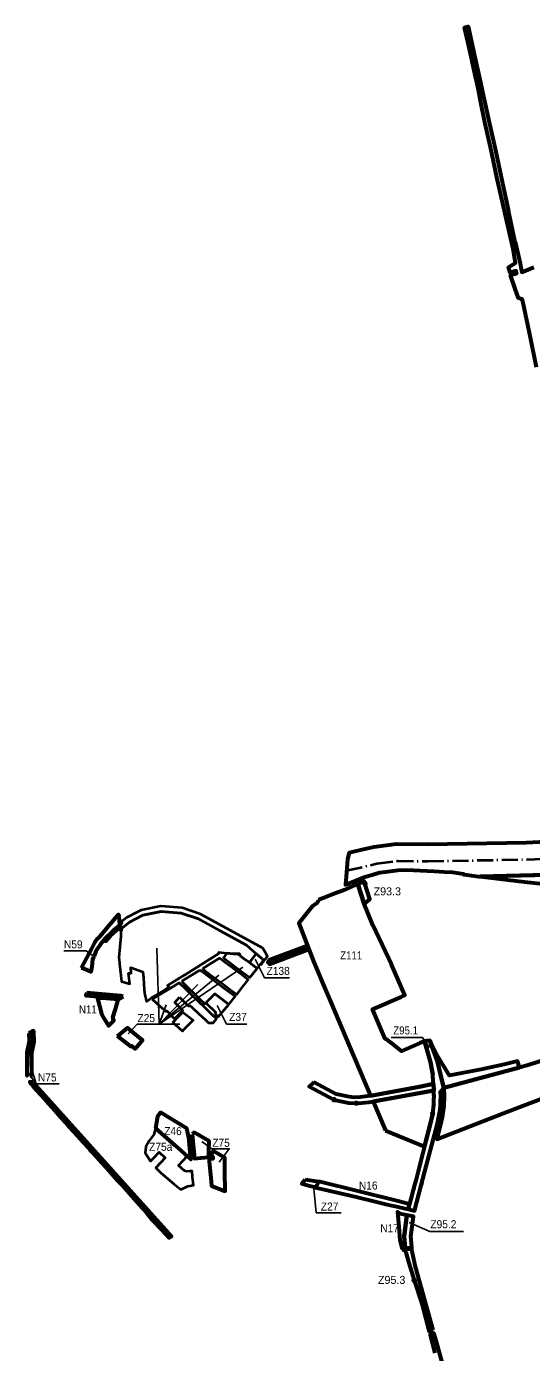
# Model space of a CAD drawing. Extents: x -650277 to -643422, y -1073980 to -1066720.
# Drawn here: x -650277 to -648765, y -1070696 to -1066720 of the extents above; entities that cross this region are included whole.
import ezdxf

# ---------------------------------------------------------------- set-up
doc = ezdxf.new("R2010")
doc.units = 0
doc.header["$LTSCALE"] = 9.6
doc.header["$PDMODE"] = 32
doc.header["$PDSIZE"] = 4.8
doc.linetypes.add('DOT_DASHED', pattern=[7.7, 5, -1.2, 0.3, -1.2])
for name, color, linetype, lineweight in [('1', 7, 'Continuous', 60), ('12', 7, 'Continuous', 60), ('13', 7, 'Continuous', 60), ('15', 7, 'Continuous', 60), ('18', 7, 'Continuous', 60), ('2', 7, 'Continuous', 40), ('24', 7, 'Continuous', 60), ('3', 7, 'Continuous', 60), ('40', 7, 'Continuous', 60), ('42', 7, 'Continuous', 60), ('48', 7, 'Continuous', 60), ('59', 7, 'Continuous', 25), ('60', 7, 'Continuous', 60), ('62', 7, 'DOT_DASHED', 40), ('63', 7, 'Continuous', 25), ('7', 7, 'Continuous', 60), ('9', 7, 'Continuous', 60)]:
    doc.layers.add(name, color=color, linetype=linetype, lineweight=lineweight)

msp = doc.modelspace()

# ---------------------------------------------------------------- linework, layer by layer
at = {"layer": '1'}
for points in [[(-650004.59, -1069747.27), (-649974.86, -1069721.96), (-649966.52, -1069728.87), (-649929.38, -1069759.65), (-649951.56, -1069785.42), (-649963, -1069776.7), (-649965, -1069778.7)], [(-649442.63, -1070176.69), (-649402.29, -1070182.92), (-649404.2, -1070187.43), (-649412.2, -1070200.71), (-649433.3, -1070195.89), (-649453.27, -1070190.02), (-649446.19, -1070180.76)]]:
    msp.add_lwpolyline(points, close=True, dxfattribs=at)
at = {"layer": '12'}
msp.add_lwpolyline([(-649891.21, -1070022.68), (-649832.007, -1070074.751), (-649784.87, -1070116.76), (-649791.31, -1070051.51), (-649797.45, -1070023.77), (-649876.31, -1069975.93), (-649884.59, -1069988.57)], close=True, dxfattribs=at)
at = {"layer": '13'}
msp.add_line((-649202.375, -1070030.469), (-649085.737, -1070078.201), dxfattribs=at)
for points in [[(-649057.868, -1069910.51), (-649239.635, -1069943.094), (-649202.375, -1070030.469)], [(-649085.737, -1070078.201), (-649066.487, -1070004.267), (-649061.139, -1069979.254), (-649061.138, -1069979.243)]]:
    msp.add_lwpolyline(points, dxfattribs=at)
msp.add_arc((-649347.129, -1069931.193), 290, 350.46253, 4.08974, dxfattribs=at)
msp.add_point((-649061.138, -1069979.243), dxfattribs=at)
at = {"layer": '15'}
msp.add_line((-649057.868, -1069910.51), (-649058.82, -1069890.548), dxfattribs=at)
for points in [[(-648749.97, -1067741.49), (-648767.84, -1067652.98), (-648791.68, -1067543.78), (-648792.97, -1067537.86), (-648804.08, -1067534.88), (-648813.94, -1067506.27), (-648827.86, -1067465.86), (-648809.65, -1067459.77), (-648809.97, -1067458.52), (-648811.21, -1067453.52), (-648811.4, -1067452.79), (-648829.54, -1067458.42), (-648834.01, -1067441.81), (-648812.91, -1067429.16), (-648820.39, -1067386.83), (-648844.16, -1067281.37), (-648845.94, -1067272.85), (-648867.82, -1067176.66), (-648884.26, -1067099.63), (-648899.1, -1067033.34), (-648905.06, -1067006.7), (-648917.76, -1066942.65), (-648924.32, -1066909.55), (-648936.7, -1066852.52), (-648944.75, -1066815.41), (-648955.15, -1066770.11), (-648965.39, -1066723.15), (-648959.88, -1066721.59), (-648954.86, -1066720.16), (-648935.19, -1066812.53), (-648918.27, -1066888.41), (-648914.11, -1066907.05), (-648893.02, -1067002.5), (-648872.31, -1067095.5), (-648851.87, -1067191.04), (-648835.29, -1067268.93), (-648833.66, -1067276.77), (-648816.06, -1067361.71), (-648813.81, -1067365.91), (-648799.58, -1067430.4), (-648796.8, -1067443.1), (-648795.88, -1067447.21), (-648794.7, -1067452.46), (-648793.71, -1067456.88), (-648757.97, -1067441.51)], [(-650096.627, -1069617.746), (-650099.55, -1069625.53), (-650002.39, -1069633.65)], [(-649987.49, -1069628.6), (-649994.913, -1069626.246), (-650096.627, -1069617.746)], [(-650002.39, -1069633.65), (-650002.65, -1069637.14), (-649987.49, -1069628.6)], [(-649417.234, -1069885.193), (-649418.94, -1069887.36), (-649430.515, -1069898.514), (-649356.458, -1069937.945)], [(-649246.81, -1069926.27), (-649278.492, -1069930.573), (-649296.851, -1069931.092), (-649310.738, -1069929.342), (-649350.222, -1069920.873), (-649417.234, -1069885.193)], [(-649058.82, -1069890.548), (-649101.89, -1069898.73), (-649246.81, -1069926.27)], [(-649356.458, -1069937.945), (-649312.646, -1069947.342), (-649289.95, -1069948.146)], [(-649289.95, -1069948.146), (-649282.437, -1069948.342), (-649251.805, -1069945.276), (-649239.635, -1069943.094), (-649057.868, -1069910.51)]]:
    msp.add_lwpolyline(points, dxfattribs=at)
for points in [[(-650025.31, -1069446.49), (-649998.512, -1069422.926), (-649999.01, -1069415.628), (-650018.873, -1069431.749), (-650043.521, -1069455.69), (-650045.72, -1069459.1), (-650040.012, -1069461.999)], [(-649547.733, -1069530.185), (-649431.761, -1069486.57), (-649435.578, -1069476.772), (-649550.53, -1069519.68), (-649554.83, -1069525), (-649551.32, -1069528.49), (-649549.69, -1069530.14), (-649548.881, -1069530.963)], [(-648800.85, -1069841.52), (-648806.946, -1069821.79), (-648846.924, -1069832.58), (-648916.03, -1069847.12), (-649010.55, -1069865.09), (-649049.22, -1069801.23), (-649069.4, -1069760.67), (-649048, -1069820), (-649032.928, -1069882.782), (-649028.017, -1069902.109)]]:
    msp.add_lwpolyline(points, close=True, dxfattribs=at)
for p in [(-649356.458, -1069937.945), (-649289.95, -1069948.146)]:
    msp.add_point(p, dxfattribs=at)
at = {"layer": '18'}
for points in [[(-649781.53, -1070041.2), (-649774.45, -1070113.92), (-649754.82, -1070111.89), (-649731.12, -1070109.96), (-649730.96, -1070094.91), (-649730.89, -1070088.96), (-649730.6, -1070061.98), (-649774.73, -1070035.58)], [(-649730.57, -1070115.76), (-649730, -1070122.01), (-649726.22, -1070162.75), (-649725.49, -1070170.64), (-649723.17, -1070195.81), (-649682.04, -1070211.58), (-649683.12, -1070154.14), (-649682.98, -1070132.1), (-649683.57, -1070112.05), (-649717.72, -1070091.61), (-649718.71, -1070093.35), (-649724.36, -1070099.03), (-649719.69, -1070108.94), (-649719.24, -1070114.87)]]:
    msp.add_lwpolyline(points, close=True, dxfattribs=at)
at = {"layer": '2'}
for points in [[(-649639.18, -1069505.96), (-649637.69, -1069506.15), (-649628.36, -1069513.11), (-649609.93, -1069526.87), (-649598.004, -1069510.814), (-649589.257, -1069499.905), (-649619, -1069474), (-649697.525, -1069431.522), (-649762.488, -1069395.854), (-649814.067, -1069377.972), (-649874.391, -1069373.859), (-649929.015, -1069384.784), (-649968.465, -1069405.189), (-649994.293, -1069425.949), (-649994.53, -1069447.61), (-650000.59, -1069511.15), (-649998.81, -1069527.07), (-649998.5, -1069529.88), (-649992.59, -1069582.88), (-649967.81, -1069590.74), (-649971.38, -1069558.79), (-649963.43, -1069557.91), (-649965.26, -1069541.51), (-649928.48, -1069554.57), (-649927.3, -1069572.44)], [(-649927.3, -1069572.44), (-649924.62, -1069608.53), (-649923.17, -1069623.14), (-649918.35, -1069643.45), (-649918.35, -1069643.45), (-649903.292, -1069632.541), (-649877.129, -1069617.006), (-649850.24, -1069600.295), (-649855.34, -1069595.8), (-649805.22, -1069564.32), (-649801.49, -1069561.98), (-649701.57, -1069499.21), (-649701.7, -1069495.89), (-649677.02, -1069498.32), (-649658.01, -1069500.19), (-649647.45, -1069500.23), (-649638.81, -1069500.26), (-649639.18, -1069505.96)], [(-649677.02, -1069498.32), (-649687.77, -1069512.44), (-649667.74, -1069527.4), (-649649.31, -1069541.16)], [(-649639.18, -1069505.96), (-649638.81, -1069500.26), (-649647.45, -1069500.23), (-649658.01, -1069500.19), (-649677.02, -1069498.32)], [(-649609.93, -1069526.87), (-649628.36, -1069513.11), (-649637.69, -1069506.15), (-649639.18, -1069505.96)], [(-649597.997, -1069510.805), (-649598.004, -1069510.814), (-649609.93, -1069526.87), (-649586.82, -1069544.11)], [(-649597.935, -1069510.728), (-649597.763, -1069510.865), (-649597.997, -1069510.805)], [(-649571.94, -1069529.24), (-649573.922, -1069527.657), (-649567, -1069519), (-649588, -1069501), (-649589.257, -1069499.905), (-649597.935, -1069510.728)], [(-649758.29, -1069549.64), (-649785.72, -1069566.56), (-649812.08, -1069582.83)], [(-649671.39, -1069651.93), (-649652.88, -1069628.36), (-649677.124, -1069610.681), (-649696.91, -1069595.47), (-649718.13, -1069579.63), (-649739.75, -1069563.48), (-649758.29, -1069549.64)], [(-649707.19, -1069577.81), (-649688.76, -1069591.57), (-649670.34, -1069605.34), (-649647.93, -1069622.07), (-649628.8, -1069597.67), (-649613.37, -1069577.98), (-649636.83, -1069560.47), (-649659.26, -1069543.71), (-649681.7, -1069526.96), (-649699.72, -1069513.5), (-649722.6, -1069527.61), (-649749.62, -1069544.29)], [(-649749.62, -1069544.29), (-649748.89, -1069546.2), (-649747.5, -1069547.71), (-649725.62, -1069564.05), (-649707.19, -1069577.81)], [(-649649.31, -1069541.16), (-649630.88, -1069554.92), (-649608.44, -1069571.69), (-649586.82, -1069544.11), (-649609.93, -1069526.87)], [(-649586.82, -1069544.11), (-649576.071, -1069530.398), (-649574.1, -1069531.97), (-649571.94, -1069529.24)], [(-649788.91, -1069654.4), (-649781.09, -1069661.69), (-649761.34, -1069680.08), (-649741.61, -1069698.46), (-649732.52, -1069706.92), (-649717.884, -1069707.295), (-649707.985, -1069695.508), (-649723.97, -1069680.13), (-649743.41, -1069661.43), (-649762.85, -1069642.73), (-649782.03, -1069624.28), (-649801.48, -1069605.57), (-649820.02, -1069587.73), (-649846.38, -1069603.8), (-649900.64, -1069636.78)], [(-649812.08, -1069582.83), (-649811.52, -1069584.44), (-649810.49, -1069585.81), (-649793.12, -1069602.51), (-649776.54, -1069618.46), (-649759.97, -1069634.4)], [(-649833.94, -1069695.239), (-649819.98, -1069680.92), (-649809.47, -1069670.13), (-649833.38, -1069646.08), (-649818.71, -1069630.64)], [(-649818.71, -1069630.64), (-649802.9, -1069645.96), (-649791, -1069657), (-649788.91, -1069654.4)], [(-649740.23, -1069647.14), (-649713.73, -1069620.32), (-649713.73, -1069620.32), (-649693.63, -1069635.33), (-649671.39, -1069651.93)], [(-649900.64, -1069636.78), (-649877.82, -1069656.83), (-649859.96, -1069672.53)], [(-649759.97, -1069634.4), (-649743.39, -1069650.35), (-649740.23, -1069647.14)], [(-649859.96, -1069672.53), (-649859.17, -1069673.22), (-649857.49, -1069671.46), (-649833.94, -1069695.239)]]:
    msp.add_lwpolyline(points, dxfattribs=at)
for points in [[(-649713.73, -1069620.32), (-649713.73, -1069620.32), (-649740.23, -1069647.14), (-649709.94, -1069676.28), (-649712.54, -1069678.98), (-649712.89, -1069679.87), (-649712.51, -1069680.75), (-649703.15, -1069689.75), (-649671.39, -1069651.93), (-649693.63, -1069635.33)], [(-649838.99, -1069706.15), (-649820.64, -1069687.33), (-649808.96, -1069675.34), (-649777.94, -1069699.2), (-649792.13, -1069713.65), (-649807.66, -1069729.46), (-649810.41, -1069732.28), (-649819.9, -1069723.61)], [(-649891.21, -1070022.68), (-649895.45, -1070042.15), (-649910.34, -1070061.29), (-649919.55, -1070079.01), (-649922.3, -1070096.9), (-649905.51, -1070122.35), (-649897.03, -1070113.07), (-649880.42, -1070094.87), (-649862.22, -1070111.54), (-649889.87, -1070141.83), (-649874.94, -1070157.19), (-649835.28, -1070191.27), (-649815.33, -1070206.63), (-649794.37, -1070197.2), (-649777.29, -1070193.57), (-649779.75, -1070168.69), (-649781.436, -1070151.591), (-649787.92, -1070152.23), (-649797.33, -1070153.41), (-649804.29, -1070150.68), (-649821.97, -1070134.58), (-649796.4, -1070106.56)]]:
    msp.add_lwpolyline(points, close=True, dxfattribs=at)
at = {"layer": '24'}
for points in [[(-649321.69, -1069307.61), (-649324.3, -1069308.59), (-649359.48, -1069321.82), (-649389.4, -1069333.35), (-649396.52, -1069336.09), (-649403.92, -1069338.26)], [(-649283.702, -1069294.132), (-649284.695, -1069291.033), (-649300.133, -1069297.95), (-649321.69, -1069307.61)], [(-649060.897, -1069861.994), (-649068, -1069825.147), (-649085.41, -1069762.44), (-649085.41, -1069762.44), (-649099.75, -1069768.575), (-649154.76, -1069792.11), (-649184.05, -1069768.45), (-649200.64, -1069756.53), (-649202.99, -1069754.99), (-649241.11, -1069665.9), (-649155.082, -1069629.097), (-649144.57, -1069624.6), (-649184.1, -1069532.2), (-649240.202, -1069414.528), (-649244.08, -1069404.753), (-649265.774, -1069350.068), (-649283.702, -1069294.132)], [(-649403.92, -1069338.26), (-649403.03, -1069340.66), (-649408.81, -1069349.89), (-649422.19, -1069357.99), (-649462.25, -1069408.32), (-649435.578, -1069476.772), (-649431.761, -1069486.57)], [(-649431.761, -1069486.57), (-649416.52, -1069525.68), (-649409.355, -1069544.517), (-649388.438, -1069594.296), (-649379.32, -1069615.71), (-649364.44, -1069650.55), (-649312.03, -1069773.33)], [(-649312.03, -1069773.33), (-649246.81, -1069926.27), (-649101.89, -1069898.73), (-649058.82, -1069890.548)]]:
    msp.add_lwpolyline(points, dxfattribs=at)
msp.add_arc((-649649.71, -1069919.176), 591.583, 2.77379, 5.54687, dxfattribs=at)
at = {"layer": '3', "lineweight": 40}
for points in [[(-649558.601, -1069502.461), (-649570.03, -1069483.83), (-649688.625, -1069418.156), (-649755.971, -1069381.179), (-649810.846, -1069362.154), (-649875.434, -1069357.751), (-649934.363, -1069369.537), (-649945.397, -1069375.277), (-649977.239, -1069391.714), (-649994.329, -1069405.451)], [(-649994.293, -1069425.949), (-649968.465, -1069405.189), (-649929.015, -1069384.784), (-649874.391, -1069373.859)], [(-649874.391, -1069373.859), (-649814.067, -1069377.972), (-649762.488, -1069395.854), (-649697.525, -1069431.522), (-649619, -1069474), (-649589.257, -1069499.905)], [(-649994.329, -1069405.451), (-649994.329, -1069405.451), (-649994.293, -1069425.949), (-649994.293, -1069425.949)], [(-649589.257, -1069499.905), (-649567, -1069519), (-649573.922, -1069527.657), (-649571.94, -1069529.24), (-649561.17, -1069515.83), (-649555.16, -1069508.07), (-649558.601, -1069502.461)]]:
    msp.add_lwpolyline(points, dxfattribs=at)
at = {"layer": '3'}
msp.add_lwpolyline([(-648722.24, -1069817.54), (-648772.48, -1069832.83), (-648800.85, -1069841.52), (-649028.017, -1069902.109), (-649027.135, -1069928.902), (-649027.953, -1069955.702), (-649032.644, -1069990.371), (-649037.411, -1070011.659), (-649048.918, -1070055.852), (-648931.057, -1070010.171), (-648849.532, -1069978.559), (-648767.83, -1069946.87), (-648562.242, -1069870.301)], dxfattribs=at)
for p in [(-649994.329, -1069405.451), (-649994.293, -1069425.949)]:
    msp.add_point(p, dxfattribs=at)
at = {"layer": '40'}
for points in [[(-650002.65, -1069637.14), (-650050.26, -1069633.65), (-650064.77, -1069633.06), (-650052.88, -1069679.49), (-650047.45, -1069690.69), (-650031.64, -1069715.9), (-650015.53, -1069700.21), (-650018.31, -1069690.89), (-650011.15, -1069665.82)], [(-649160.748, -1070243.413), (-649402.29, -1070182.92), (-649404.2, -1070187.43), (-649412.2, -1070200.71), (-649412.2, -1070200.71), (-649408.24, -1070201.62), (-649372.69, -1070209.74), (-649289.83, -1070229.16), (-649229.8, -1070243.94), (-649197.55, -1070251.65), (-649164.91, -1070258.55), (-649160.54, -1070259.96), (-649134.294, -1070266.095), (-649130.712, -1070250.935)]]:
    msp.add_lwpolyline(points, close=True, dxfattribs=at)
at = {"layer": '42'}
msp.add_lwpolyline([(-650112.18, -1069542.11), (-650081.29, -1069484.35), (-650072.5, -1069466.44), (-650063.12, -1069453.54), (-650062.17, -1069454.05), (-650060.29, -1069451.7), (-650057.49, -1069448.18), (-650026.33, -1069411.47), (-650003.73, -1069384.71), (-650002.11, -1069382.8), (-650001.13, -1069388.13), (-649999.95, -1069397.98), (-649999.01, -1069415.628), (-650018.873, -1069431.749), (-650043.521, -1069455.69), (-650045.72, -1069459.1), (-650055.612, -1069471.639), (-650066.897, -1069487.541), (-650069.369, -1069492.132), (-650074.75, -1069506.133), (-650076.365, -1069510.333), (-650079.264, -1069517.874), (-650080.302, -1069525.418), (-650080.802, -1069530.768), (-650082.963, -1069544.736), (-650084.345, -1069554.773)], close=True, dxfattribs=at)
at = {"layer": '48'}
for points in [[(-650270.059, -1069739.232), (-650269.449, -1069762.714), (-650276.214, -1069796.532), (-650275.76, -1069865.474), (-650274.95, -1069865.62), (-650273.87, -1069809.74), (-650273.78, -1069805.2), (-650273.58, -1069794.48), (-650270.15, -1069778.65), (-650267.22, -1069765.1), (-650265.37, -1069741.61), (-650264.91, -1069735.69)], [(-650260.645, -1069868.536), (-650260.748, -1069867.327), (-650261.204, -1069797.969), (-650254.411, -1069764.006), (-650255.21, -1069733.253), (-650255.716, -1069731.162), (-650259.97, -1069732.29), (-650258.74, -1069750.62), (-650257.77, -1069765.2), (-650262.93, -1069794.84), (-650262.77, -1069805.54), (-650262.7, -1069809.89), (-650261.8, -1069868.33)], [(-650257.713, -1069885.547), (-650266.89, -1069883.7), (-650266.68, -1069886.78), (-650262.64, -1069891.57), (-650257.16, -1069898.07), (-650224.71, -1069934.41), (-650209.51, -1069951.43), (-650192.51, -1069970.47), (-650174.3, -1069990.86), (-650157.87, -1070009.26), (-650151.03, -1070016.84), (-650134.26, -1070035.45), (-650106.76, -1070065.96), (-650091.89, -1070082.46), (-650087.18, -1070087.68), (-650076.72, -1070099.29), (-650051.33, -1070127.45), (-650037.78, -1070142.48), (-650018.41, -1070163.97), (-650005.3, -1070178.51), (-649990.95, -1070194.43), (-649977.05, -1070209.85), (-649946.39, -1070243.87), (-649930.46, -1070261.54), (-649924.15, -1070268.55), (-649913.03, -1070282.44), (-649901.59, -1070296.73), (-649871.28, -1070329.01), (-649850.04, -1070351.64), (-649843.513, -1070347.685)]]:
    msp.add_lwpolyline(points, close=True, dxfattribs=at)
at = {"layer": '59'}
for p, q in [((-649880, -1069711), (-649887, -1069483)), ((-649880, -1069711), (-649629, -1069540)), ((-649880, -1069711), (-649701, -1069564)), ((-649880, -1069711), (-649764, -1069592)), ((-649880, -1069711), (-649818, -1069711)), ((-649410, -1070277), (-649417.769, -1070193.978)), ((-649335, -1070277), (-649410, -1070277))]:
    msp.add_line(p, q, dxfattribs=at)
for points in [[(-649490, -1069572), (-649565, -1069572), (-649593, -1069516)], [(-649946, -1069711), (-649880, -1069711), (-649859, -1069653)], [(-649618, -1069711), (-649678, -1069711), (-649706, -1069655)]]:
    msp.add_lwpolyline(points, dxfattribs=at)
at = {"layer": '60'}
for p, q in [((-649058.858, -1069889.759), (-649057.868, -1069910.51)), ((-649057.134, -1069932.873), (-649057.868, -1069910.51)), ((-649146.163, -1070347.543), (-649145.424, -1070357.637))]:
    msp.add_line(p, q, dxfattribs=at)
for points in [[(-648721.315, -1069164.952), (-648781.015, -1069167.44), (-649076.02, -1069172.683), (-649169.781, -1069171.432), (-649237.512, -1069180.731), (-649277.021, -1069189.913), (-649306.455, -1069196.754), (-649311.633, -1069197.958), (-649316.47, -1069216.91), (-649321.32, -1069281.47), (-649322.09, -1069291.73), (-649322.22, -1069293.54), (-649319.72, -1069292.47), (-649267.5, -1069270.41), (-649242.5, -1069263.3), (-649220.18, -1069257.03), (-649202.63, -1069254.4), (-649165.62, -1069249.43), (-649139.63, -1069248.73), (-649056.95, -1069252.55), (-649026.955, -1069254.366), (-649001.3, -1069255.92), (-648968.49, -1069260.36), (-648968.05, -1069263.06), (-648965.8, -1069262.75), (-648937.91, -1069266.51), (-648924.13, -1069268.21), (-648918.889, -1069268.875), (-648673.267, -1069262.895)], [(-649061.138, -1069979.243), (-649061.138, -1069979.243), (-649061.139, -1069979.254), (-649066.487, -1070004.267), (-649098.65, -1070127.795), (-649110.925, -1070177.113), (-649114.174, -1070189.816), (-649130.712, -1070250.935), (-649134.294, -1070266.095), (-649115.159, -1070270.568), (-649095.152, -1070193.731), (-649093.095, -1070186.132), (-649095.152, -1070193.731), (-649080.924, -1070137.409), (-649080.38, -1070136.996), (-649047.131, -1070009.304), (-649042.468, -1069988.477), (-649042.468, -1069988.477), (-649039.966, -1069973.035), (-649037.98, -1069956.626), (-649037.322, -1069942.129), (-649037.137, -1069928.996), (-649037.665, -1069912.977), (-649028.017, -1069902.109), (-649032.928, -1069882.782), (-649048, -1069820), (-649069.4, -1069760.67), (-649085.41, -1069762.44), (-649068, -1069825.147), (-649060.897, -1069861.994)], [(-649138.43, -1070283.6), (-649146.163, -1070347.543), (-649146.163, -1070347.543)], [(-649125.503, -1070355.837), (-649126.069, -1070348.097), (-649118.257, -1070287.455), (-649138.43, -1070283.6)], [(-649059.951, -1070628.223), (-649112.14, -1070439.152), (-649123.138, -1070388.16), (-649123.385, -1070384.775), (-649145.73, -1070387.91)], [(-649145.424, -1070357.637), (-649143.633, -1070382.123), (-649123.693, -1070380.572), (-649125.503, -1070355.837)], [(-649145.73, -1070387.91), (-649141.48, -1070394.84), (-649132.07, -1070426.81), (-649116.56, -1070479.19)], [(-649116.56, -1070479.19), (-649093.2, -1070549.1), (-649071.33, -1070632.6), (-649059.951, -1070628.223)], [(-649025.129, -1070754.377), (-649047.11, -1070674.743), (-649050.081, -1070663.981), (-649057.338, -1070637.689), (-649068.65, -1070642.23), (-649068.65, -1070642.23), (-649054.31, -1070696.44)]]:
    msp.add_lwpolyline(points, dxfattribs=at)
msp.add_lwpolyline([(-648730.66, -1069290.43), (-648656.242, -1069297.116), (-648673.267, -1069262.895), (-648761.189, -1069265.035), (-648918.889, -1069268.875), (-648909.86, -1069270.02), (-648861.49, -1069275.34), (-648785.92, -1069284.2), (-648730.66, -1069290.43)], close=True, dxfattribs=at)
for centre, radius, start, end in [((-649633.43, -1069918.001), 575.266, 2.81398, 5.58706), ((-649347.129, -1069931.193), 290, 350.46253, 4.08974), ((-649347.129, -1069931.193), 290, 359.66809, 4.08974)]:
    msp.add_arc(centre, radius, start, end, dxfattribs=at)
for p in [(-649145.73, -1070387.91), (-649116.56, -1070479.19)]:
    msp.add_point(p, dxfattribs=at)
at = {"layer": '62'}
msp.add_lwpolyline([(-649319.032, -1069251.01), (-649228.433, -1069229.954), (-649166.697, -1069221.478), (-649075.909, -1069222.689), (-648779.53, -1069217.422), (-648667.088, -1069212.737)], dxfattribs=at)
at = {"layer": '63'}
for p, q in [((-649973, -1069740), (-649946, -1069711)), ((-650248, -1069890), (-650277, -1069850)), ((-650248, -1069890), (-650261, -1069847))]:
    msp.add_line(p, q, dxfattribs=at)
for points in [[(-650165, -1069491), (-650099, -1069491), (-650081, -1069504)], [(-649185, -1069751), (-649092, -1069751), (-649071, -1069781)], [(-650243, -1069909), (-650248, -1069890), (-650179, -1069890)], [(-649752, -1070063), (-649722, -1070085), (-649670, -1070085), (-649700, -1070125)], [(-648969, -1070333), (-649070, -1070333), (-649132, -1070306)]]:
    msp.add_lwpolyline(points, dxfattribs=at)
at = {"layer": '7'}
msp.add_lwpolyline([(-649138.43, -1070283.6), (-649159.78, -1070279.52), (-649166.86, -1070273.48), (-649162.91, -1070317.47), (-649159.19, -1070358.82), (-649153.64, -1070382.9), (-649148.23, -1070382.48), (-649143.633, -1070382.123), (-649146.163, -1070347.543)], close=True, dxfattribs=at)
at = {"layer": '9'}
msp.add_line((-649283.702, -1069294.132), (-649265.774, -1069350.068), dxfattribs=at)
for points in [[(-649264.156, -1069289.589), (-649266.331, -1069282.804), (-649284.695, -1069291.033), (-649283.702, -1069294.132)], [(-649265.774, -1069350.068), (-649249.069, -1069336.66), (-649264.156, -1069289.589)]]:
    msp.add_lwpolyline(points, dxfattribs=at)
for p in [(-649283.702, -1069294.132), (-649264.156, -1069289.589)]:
    msp.add_point(p, dxfattribs=at)

# ---------------------------------------------------------------- texts
at = {"layer": '59', "width": 0.95}
for s, p in [('Z138', (-649558.387, -1069563.603)), ('Z25', (-649945, -1069705)), ('Z37', (-649670.387, -1069701.603)), ('Z75a', (-649910, -1070091)), ('Z27', (-649396, -1070270))]:
    msp.add_text(s, height=24, dxfattribs=at).set_placement(p)
at = {"layer": '63'}
for s, p in [('Z93.3', (-649238, -1069325)), ('Z95.3', (-649225, -1070490))]:
    msp.add_text(s, height=24, dxfattribs=at).set_placement(p)
for s, width, p in [('N59', 0.95, (-650165, -1069484)), ('Z111', 0.9, (-649338, -1069517)), ('N11', 0.9, (-650120, -1069679)), ('Z95.1', 0.9, (-649179, -1069742)), ('N75', 0.95, (-650243, -1069883)), ('Z46', 0.95, (-649865, -1070044)), ('Z75', 0.95, (-649721, -1070079)), ('N16', 0.95, (-649282, -1070207)), ('Z95.2', 0.95, (-649068, -1070323)), ('N17', 0.95, (-649218, -1070335))]:
    msp.add_text(s, height=24, dxfattribs=dict(at, width=width)).set_placement(p)

doc.saveas('drawing.dxf')
